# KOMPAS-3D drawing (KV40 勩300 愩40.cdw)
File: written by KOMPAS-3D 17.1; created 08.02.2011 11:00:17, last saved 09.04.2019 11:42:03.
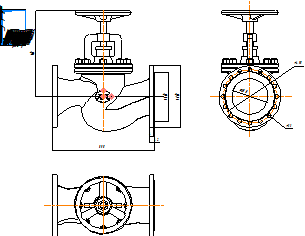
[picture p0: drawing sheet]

Title block, sheet 1: name: KV 40 Ду300; material: Внимание! Данный продукт является объектом авторского права ООО «Торговый Дом АДЛ». / Запрещается изменение, копирование, распространение / (в том числе путем копирования на другие сайты и ресурсы в Интернете) / или любое иное использование информации и объектов без предварительного / согласия правообладателя (ООО «Торговый Дом АДЛ»).; scale: 1:1; sheets: 1; organisation: ООО "Торговый дом АДЛ"; sheet format: A4; stored path: \\adlc.lan\data\АДЛ_ПКД\3D-модели\ADL production\Вентили ГРАНВЕНТ\KV40\KOMPAS 2D\KV 40 Ду300.cdw

Views: Спереди 1, Проекционный вид 2, Проекционный вид 3
Dimensions and other numbers on the sheet: 410; 515; 850; 710; 4; 42; 450; 33; 300; 1:1; 1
